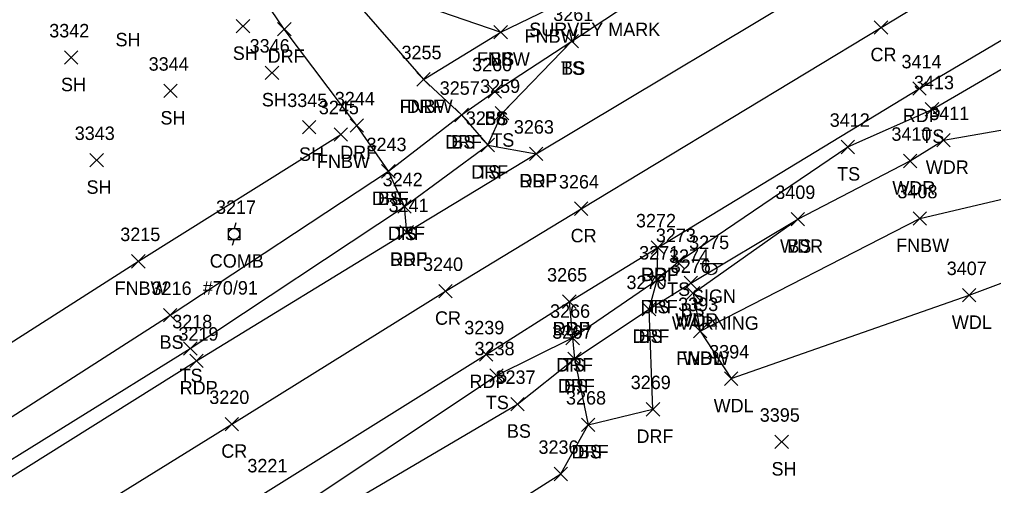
# Model space of a CAD drawing. Extents: x 1443590 to 1445966, y 578314 to 580556.
# Drawn here: x 1443948 to 1444092.8, y 578792.7 to 578862 of the extents above; entities that cross this region are included whole.
import ezdxf

# ---------------------------------------------------------------- set-up
doc = ezdxf.new("R2010")
doc.units = 0
for name, color, linetype in [('L_A', 7, 'Continuous'), ('L_I', 7, 'Continuous'), ('L_TIC', 7, 'Continuous'), ('LAWA', 7, 'Continuous'), ('LELB', 7, 'Continuous'), ('LFNC', 7, 'Continuous'), ('P_A', 7, 'Continuous'), ('P_I', 7, 'Continuous'), ('P_TIC', 7, 'Continuous'), ('PET', 7, 'Continuous'), ('PRC', 7, 'Continuous'), ('R_A', 7, 'Continuous'), ('R_I', 7, 'Continuous'), ('R_TIC', 7, 'Continuous'), ('RDF', 7, 'Continuous'), ('S_A', 7, 'Continuous'), ('S_C', 7, 'Continuous'), ('S_I', 7, 'Continuous'), ('SSGN', 7, 'Continuous'), ('U_A', 7, 'Continuous'), ('U_C', 7, 'Continuous'), ('U_I', 7, 'Continuous'), ('UP', 7, 'Continuous')]:
    doc.layers.add(name, color=color, linetype=linetype)

msp = doc.modelspace()

# ---------------------------------------------------------------- linework, layer by layer
at = {"layer": 'L_TIC'}
for points in [[(1443980.21, 578859.99), (1443982.21, 578861.99)], [(1443982.21, 578859.99), (1443980.21, 578861.99)], [(1444018.51, 578859.12), (1444020.51, 578861.12)], [(1444020.51, 578859.12), (1444018.51, 578861.12)], [(1444018.51, 578859.12), (1444020.51, 578861.12)], [(1444020.51, 578859.12), (1444018.51, 578861.12)], [(1444029.07, 578857.77), (1444031.07, 578859.77)], [(1444031.07, 578857.77), (1444029.07, 578859.77)], [(1444029.07, 578857.77), (1444031.07, 578859.77)], [(1444031.07, 578857.77), (1444029.07, 578859.77)], [(1443954.67, 578855.33), (1443956.67, 578857.33)], [(1443956.67, 578855.33), (1443954.67, 578857.33)], [(1443984.52, 578853.07), (1443986.52, 578855.07)], [(1443986.52, 578853.07), (1443984.52, 578855.07)], [(1444007.03, 578852.09), (1444009.03, 578854.09)], [(1444009.03, 578852.09), (1444007.03, 578854.09)], [(1443969.45, 578850.38), (1443971.45, 578852.38)], [(1443971.45, 578850.38), (1443969.45, 578852.38)], [(1444017.65, 578850.29), (1444019.65, 578852.29)], [(1444019.65, 578850.29), (1444017.65, 578852.29)], [(1444012.71, 578846.8), (1444014.71, 578848.8)], [(1444014.71, 578846.8), (1444012.71, 578848.8)], [(1444018.71, 578847.08), (1444020.71, 578849.08)], [(1444020.71, 578847.08), (1444018.71, 578849.08)], [(1444082.63, 578847.63), (1444084.63, 578849.63)], [(1444084.63, 578847.63), (1444082.63, 578849.63)], [(1443990.05, 578844.98), (1443992.05, 578846.98)], [(1443992.05, 578844.98), (1443990.05, 578846.98)], [(1443994.74, 578843.91), (1443996.74, 578845.91)], [(1443996.74, 578843.91), (1443994.74, 578845.91)], [(1444016.59, 578842.33), (1444018.59, 578844.33)], [(1444018.59, 578842.33), (1444016.59, 578844.33)], [(1444084.34, 578843.04), (1444086.34, 578845.04)], [(1444086.34, 578843.04), (1444084.34, 578845.04)], [(1444070.11, 578842.04), (1444072.11, 578844.04)], [(1444072.11, 578842.04), (1444070.11, 578844.04)], [(1443958.46, 578840.08), (1443960.46, 578842.08)], [(1443960.46, 578840.08), (1443958.46, 578842.08)], [(1444079.37, 578839.96), (1444081.37, 578841.96)], [(1444081.37, 578839.96), (1444079.37, 578841.96)], [(1444001.82, 578838.42), (1444003.82, 578840.42)], [(1444003.82, 578838.42), (1444001.82, 578840.42)], [(1444004.23, 578833.2), (1444006.23, 578835.2)], [(1444006.23, 578833.2), (1444004.23, 578835.2)], [(1444062.67, 578831.31), (1444064.67, 578833.31)], [(1444064.67, 578831.31), (1444062.67, 578833.31)], [(1444062.67, 578831.31), (1444064.67, 578833.31)], [(1444064.67, 578831.31), (1444062.67, 578833.31)], [(1444080.82, 578831.41), (1444082.82, 578833.41)], [(1444082.82, 578831.41), (1444080.82, 578833.41)], [(1443964.66, 578825.05), (1443966.66, 578827.05)], [(1443966.66, 578825.05), (1443964.66, 578827.05)], [(1444044.84, 578824.91), (1444046.84, 578826.91)], [(1444046.84, 578824.91), (1444044.84, 578826.91)], [(1444041.78, 578822.31), (1444043.78, 578824.31)], [(1444043.78, 578822.31), (1444041.78, 578824.31)], [(1444046.79, 578821.82), (1444048.79, 578823.82)], [(1444048.79, 578821.82), (1444046.79, 578823.82)], [(1444047.1, 578820.32), (1444049.1, 578822.32)], [(1444049.1, 578820.32), (1444047.1, 578822.32)], [(1444047.1, 578820.32), (1444049.1, 578822.32)], [(1444049.1, 578820.32), (1444047.1, 578822.32)], [(1444088.15, 578820), (1444090.15, 578822)], [(1444090.15, 578820), (1444088.15, 578822)], [(1444040.56, 578817.92), (1444042.56, 578819.92)], [(1444042.56, 578817.92), (1444040.56, 578819.92)], [(1443969.37, 578817.04), (1443971.37, 578819.04)], [(1443971.37, 578817.04), (1443969.37, 578819.04)], [(1444048.15, 578814.65), (1444050.15, 578816.65)], [(1444050.15, 578814.65), (1444048.15, 578816.65)], [(1444048.15, 578814.65), (1444050.15, 578816.65)], [(1444050.15, 578814.65), (1444048.15, 578816.65)], [(1444029.21, 578813.65), (1444031.21, 578815.65)], [(1444031.21, 578813.65), (1444029.21, 578815.65)], [(1443972.38, 578812.08), (1443974.38, 578814.08)], [(1443974.38, 578812.08), (1443972.38, 578814.08)], [(1444029.48, 578810.54), (1444031.48, 578812.54)], [(1444031.48, 578810.54), (1444029.48, 578812.54)], [(1444017.89, 578808.07), (1444019.89, 578810.07)], [(1444019.89, 578808.07), (1444017.89, 578810.07)], [(1444052.76, 578807.6), (1444054.76, 578809.6)], [(1444054.76, 578807.6), (1444052.76, 578809.6)], [(1444021, 578803.82), (1444023, 578805.82)], [(1444023, 578803.82), (1444021, 578805.82)], [(1444031.53, 578800.75), (1444033.53, 578802.75)], [(1444033.53, 578800.75), (1444031.53, 578802.75)], [(1444060.28, 578798.2), (1444062.28, 578800.2)], [(1444062.28, 578798.2), (1444060.28, 578800.2)], [(1444027.44, 578793.43), (1444029.44, 578795.43)], [(1444029.44, 578793.43), (1444027.44, 578795.43)]]:
    msp.add_lwpolyline(points, dxfattribs=at)
at = {"layer": 'LAWA'}
for points in [[(1444048.1, 578821.32), (1444063.67, 578832.31), (1444080.37, 578840.96), (1444085.34, 578844.04), (1444109.18, 578848.22), (1444135.34, 578861.47), (1444163.11, 578880.72), (1444179.57, 578893.49), (1444193.41, 578903.29), (1444214.9, 578918.81), (1444217.38, 578923.7), (1444222.65, 578929.51), (1444230.19, 578931.19), (1444234.32, 578936.96), (1444238.17, 578925.12), (1444234.94, 578915.96)], [(1444048.1, 578821.32), (1444049.15, 578815.65), (1444053.76, 578808.6), (1444089.15, 578821), (1444115.87, 578831.04), (1444149.45, 578834.28), (1444175.65, 578843.43), (1444202.18, 578846.34), (1444218.5, 578835.02), (1444228, 578822.21), (1444234.72, 578800.9), (1444237.58, 578781.4), (1444240.48, 578772.04)]]:
    msp.add_lwpolyline(points, dxfattribs=at)
at = {"layer": 'LELB'}
for points in [[(1443938.52, 578791.48), (1443973.38, 578813.08), (1444005.23, 578834.2), (1444017.59, 578843.33), (1444019.71, 578848.08), (1444030.07, 578858.77), (1444048.25, 578870.77), (1444059.47, 578877.54), (1444084.03, 578888.38), (1444116.13, 578900.62), (1444133.65, 578911.54), (1444146.41, 578917.11), (1444149.51, 578920.45), (1444149.93, 578925.58), (1444153.52, 578930.88), (1444162.25, 578930.68), (1444174.13, 578936.01), (1444189.83, 578945.52), (1444198.3, 578950.86), (1444200.25, 578947.99), (1444203.06, 578948.48)], [(1443615.53, 578549.09), (1443647.15, 578571.87), (1443656.71, 578577.24), (1443699.78, 578605.86), (1443739.16, 578631.36), (1443774.01, 578653.63), (1443806.33, 578675.43), (1443846.66, 578699.7), (1443880.84, 578720.78), (1443915.45, 578744.08), (1443953.64, 578767.01), (1443986.4, 578787.39), (1444018.89, 578809.07), (1444030.21, 578814.65), (1444042.78, 578823.31), (1444045.84, 578825.91), (1444071.11, 578843.04), (1444083.63, 578848.63), (1444101.33, 578858.93), (1444132.81, 578873.64), (1444159.48, 578890.92), (1444189.04, 578910.16), (1444210.73, 578922.71), (1444214.87, 578926.32)], [(1443994.39, 578868.79), (1444019.51, 578860.12)], [(1443598.08, 578578.97), (1443630.15, 578597.86), (1443636.56, 578601.95), (1443682.3, 578633.7), (1443721.18, 578657.98), (1443758.09, 578682.95), (1443790.68, 578702.48), (1443830, 578727.26), (1443864.08, 578751.06), (1443899.99, 578773.27), (1443935.63, 578795.8), (1443970.37, 578818.04), (1444002.82, 578839.42), (1444013.71, 578847.8), (1444018.65, 578851.29), (1444030.07, 578858.77)], [(1443617.38, 578545.93), (1443649.59, 578568.34), (1443659.37, 578572.13), (1443703.15, 578599.79), (1443742.08, 578627.42), (1443775.99, 578650.05), (1443809.17, 578670.17), (1443847.87, 578696.41), (1443882.88, 578718.02), (1443917, 578740.41), (1443955.43, 578764.28), (1443988.08, 578784.83), (1444022, 578804.82), (1444030.48, 578811.54), (1444041.56, 578818.92), (1444047.79, 578822.82), (1444063.67, 578832.31)], [(1443707.24, 578593.68), (1443747.78, 578617.37), (1443781.43, 578641.01), (1443814.18, 578660.08), (1443852.96, 578688.17), (1443888.41, 578709.13), (1443921.62, 578733.3), (1443961.2, 578754.18), (1443994.65, 578773), (1444028.44, 578794.43), (1444032.53, 578801.75)]]:
    msp.add_lwpolyline(points, dxfattribs=at)
at = {"layer": 'LFNC'}
for points in [[(1444008.03, 578853.09), (1444019.51, 578860.12), (1444026.6, 578863.53), (1444041.29, 578874.04), (1444045.2, 578875.82), (1444057.59, 578882.55), (1444080.64, 578894.32), (1444110.52, 578908.89), (1444116.81, 578913.3)], [(1444049.15, 578815.65), (1444081.82, 578832.41), (1444112.31, 578839.58), (1444143.92, 578843.39), (1444172.92, 578854.56)], [(1443632.19, 578609.42), (1443678.23, 578640.34), (1443716.84, 578665.76), (1443753.55, 578689.96), (1443784.42, 578710.35), (1443825.24, 578737.4), (1443860.1, 578759.1), (1443895.87, 578781.95), (1443931.05, 578803.95), (1443965.66, 578826.05), (1443995.74, 578844.91)]]:
    msp.add_lwpolyline(points, dxfattribs=at)
at = {"layer": 'P_TIC'}
for points in [[(1444075.05, 578859.79), (1444077.05, 578861.79)], [(1444077.05, 578859.79), (1444075.05, 578861.79)], [(1444080.78, 578850.73), (1444082.78, 578852.73)], [(1444082.78, 578850.73), (1444080.78, 578852.73)], [(1444023.78, 578841.02), (1444025.78, 578843.02)], [(1444025.78, 578841.02), (1444023.78, 578843.02)], [(1444030.47, 578832.87), (1444032.47, 578834.87)], [(1444032.47, 578832.87), (1444030.47, 578834.87)], [(1444004.54, 578829.37), (1444006.54, 578831.37)], [(1444006.54, 578829.37), (1444004.54, 578831.37)], [(1444041.88, 578827.09), (1444043.88, 578829.09)], [(1444043.88, 578827.09), (1444041.88, 578829.09)], [(1444010.31, 578820.61), (1444012.31, 578822.61)], [(1444012.31, 578820.61), (1444010.31, 578822.61)], [(1444028.71, 578819.04), (1444030.71, 578821.04)], [(1444030.71, 578819.04), (1444028.71, 578821.04)], [(1443973.31, 578810.25), (1443975.31, 578812.25)], [(1443975.31, 578810.25), (1443973.31, 578812.25)], [(1444016.37, 578811.19), (1444018.37, 578813.19)], [(1444018.37, 578811.19), (1444016.37, 578813.19)], [(1443978.55, 578800.84), (1443980.55, 578802.84)], [(1443980.55, 578800.84), (1443978.55, 578802.84)]]:
    msp.add_lwpolyline(points, dxfattribs=at)
at = {"layer": 'PET'}
for points in [[(1443601.36, 578573.38), (1443632.23, 578593.39), (1443639.99, 578598.09), (1443685.58, 578628.02), (1443724.74, 578653.09), (1443761.98, 578676.74), (1443793.7, 578697.2), (1443832.46, 578722.27), (1443867.74, 578744.22), (1443903.66, 578767.03), (1443939.74, 578789.58), (1443974.31, 578811.25), (1444005.54, 578830.37), (1444024.78, 578842.02), (1444070.83, 578869.64), (1444088.82, 578880.14), (1444118.02, 578897.28), (1444147.48, 578914.76), (1444176.13, 578931.32), (1444203.82, 578947.29), (1444208.88, 578939.04), (1444214.07, 578930.35)], [(1443612.4, 578554.37), (1443645.04, 578575.45), (1443657.24, 578583.2), (1443697.44, 578609.18), (1443737.28, 578634.55), (1443772.29, 578657.29), (1443804.75, 578678.07), (1443844.06, 578703.73), (1443878.04, 578725.08), (1443913.76, 578747.61), (1443950.95, 578770.86), (1443984.55, 578791.67), (1444017.37, 578812.19), (1444029.71, 578820.04), (1444042.88, 578828.09), (1444081.78, 578851.73), (1444099.65, 578862.29), (1444128.94, 578879.48), (1444156.82, 578896.17), (1444186.94, 578914.09), (1444214.07, 578930.35)]]:
    msp.add_lwpolyline(points, dxfattribs=at)
at = {"layer": 'PRC'}
msp.add_lwpolyline([(1443607.19, 578563.71), (1443645.74, 578588.68), (1443691.8, 578618.64), (1443730.92, 578643.94), (1443766.58, 578667.23), (1443799.08, 578688.06), (1443838.06, 578712.83), (1443872.72, 578734.91), (1443908.54, 578757.41), (1443944.72, 578780.26), (1443979.55, 578801.84), (1444011.31, 578821.61), (1444031.47, 578833.87), (1444076.05, 578860.79), (1444093.92, 578871.67), (1444123.23, 578888.92), (1444152.19, 578905.95), (1444180.96, 578922.73), (1444208.88, 578939.04)], dxfattribs=at)
at = {"layer": 'R_TIC'}
for points in [[(1443986.35, 578859.55), (1443988.35, 578861.55)], [(1443988.35, 578859.55), (1443986.35, 578861.55)], [(1444007.03, 578852.09), (1444009.03, 578854.09)], [(1444009.03, 578852.09), (1444007.03, 578854.09)], [(1444012.71, 578846.8), (1444014.71, 578848.8)], [(1444014.71, 578846.8), (1444012.71, 578848.8)], [(1443997.12, 578845.23), (1443999.12, 578847.23)], [(1443999.12, 578845.23), (1443997.12, 578847.23)], [(1444016.59, 578842.33), (1444018.59, 578844.33)], [(1444018.59, 578842.33), (1444016.59, 578844.33)], [(1444023.78, 578841.02), (1444025.78, 578843.02)], [(1444025.78, 578841.02), (1444023.78, 578843.02)], [(1444001.82, 578838.42), (1444003.82, 578840.42)], [(1444003.82, 578838.42), (1444001.82, 578840.42)], [(1444004.23, 578833.2), (1444006.23, 578835.2)], [(1444006.23, 578833.2), (1444004.23, 578835.2)], [(1444004.54, 578829.37), (1444006.54, 578831.37)], [(1444006.54, 578829.37), (1444004.54, 578831.37)], [(1444041.88, 578827.09), (1444043.88, 578829.09)], [(1444043.88, 578827.09), (1444041.88, 578829.09)], [(1444041.78, 578822.31), (1444043.78, 578824.31)], [(1444043.78, 578822.31), (1444041.78, 578824.31)], [(1444028.71, 578819.04), (1444030.71, 578821.04)], [(1444030.71, 578819.04), (1444028.71, 578821.04)], [(1444040.56, 578817.92), (1444042.56, 578819.92)], [(1444042.56, 578817.92), (1444040.56, 578819.92)], [(1444029.21, 578813.65), (1444031.21, 578815.65)], [(1444031.21, 578813.65), (1444029.21, 578815.65)], [(1444029.48, 578810.54), (1444031.48, 578812.54)], [(1444031.48, 578810.54), (1444029.48, 578812.54)], [(1444041.15, 578803.05), (1444043.15, 578805.05)], [(1444043.15, 578803.05), (1444041.15, 578805.05)], [(1444031.53, 578800.75), (1444033.53, 578802.75)], [(1444033.53, 578800.75), (1444031.53, 578802.75)]]:
    msp.add_lwpolyline(points, dxfattribs=at)
at = {"layer": 'RDF'}
for points in [[(1443966.18, 578906.12), (1443972.09, 578897.91), (1443978.46, 578889.4), (1443989.8, 578874.36), (1443994.39, 578868.79), (1444008.03, 578853.09), (1444013.71, 578847.8), (1444017.59, 578843.33), (1444024.78, 578842.02)], [(1444005.54, 578830.37), (1444005.23, 578834.2), (1444002.82, 578839.42), (1443998.12, 578846.23), (1443987.35, 578860.55), (1443977.51, 578875.06), (1443965.28, 578891.59), (1443957.31, 578900.74)], [(1444029.71, 578820.04), (1444030.21, 578814.65), (1444030.48, 578811.54), (1444032.53, 578801.75), (1444042.15, 578804.05), (1444041.56, 578818.92), (1444042.78, 578823.31), (1444042.88, 578828.09)]]:
    msp.add_lwpolyline(points, dxfattribs=at)
at = {"layer": 'SSGN'}
for p, q in [((1444049.16, 578825.71), (1444052.49, 578825.71)), ((1444050.8, 578824.88), (1444050.8, 578824.88))]:
    msp.add_line(p, q, dxfattribs=at)
msp.add_circle((1444050.8, 578824.88), 0.833, dxfattribs=at)
at = {"layer": 'UP'}
for p, q in [((1443980.14, 578831.76), (1443979.89, 578830.93)), ((1443979.05, 578829.26), (1443979.05, 578830.93)), ((1443979.05, 578830.93), (1443980.72, 578830.93)), ((1443979.89, 578830.1), (1443979.89, 578830.1)), ((1443980.72, 578830.93), (1443980.72, 578829.26)), ((1443980.72, 578829.26), (1443979.05, 578829.26)), ((1443979.64, 578828.43), (1443979.89, 578829.26))]:
    msp.add_line(p, q, dxfattribs=at)
msp.add_circle((1443979.89, 578830.1), 0.833, dxfattribs=at)

# ---------------------------------------------------------------- texts
at = {"layer": 'L_A'}
for s, p in [('SH', (1443962.26, 578858)), ('FNBW', (1444023.07, 578858.53)), ('SH', (1443979.69, 578855.99)), ('FNBW', (1444015.98, 578855.12)), ('BS', (1444017.95, 578855.12)), ('TS', (1444028.48, 578853.77)), ('BS', (1444028.51, 578853.77)), ('SH', (1443954.16, 578851.33)), ('SH', (1443984.01, 578849.07)), ('FNBW', (1444004.5, 578848.09)), ('SH', (1443968.94, 578846.38)), ('BS', (1444017.09, 578846.29)), ('TS', (1444082.04, 578843.63)), ('BS', (1444012.16, 578842.8)), ('TS', (1444018.12, 578843.08)), ('SH', (1443989.54, 578840.98)), ('FNBW', (1443992.21, 578839.91)), ('TS', (1444016, 578838.33)), ('TS', (1444069.52, 578838.04)), ('WDR', (1444082.7, 578839.04)), ('SH', (1443957.95, 578836.08)), ('WDR', (1444077.73, 578835.96)), ('BS', (1444001.27, 578834.42)), ('TS', (1444003.63, 578829.2)), ('WDR', (1444061.04, 578827.31)), ('BS', (1444062.12, 578827.31)), ('FNBW', (1444078.29, 578827.41)), ('FNBW', (1443962.13, 578821.05)), ('TS', (1444044.25, 578820.91)), ('TS', (1444041.19, 578818.31)), ('BS', (1444046.23, 578817.82)), ('WDR', (1444045.47, 578816.32)), ('WDL', (1444045.52, 578816.32)), ('WDL', (1444086.57, 578816)), ('BS', (1444040, 578813.92)), ('BS', (1443968.81, 578813.04)), ('FNBW', (1444045.62, 578810.65)), ('WDL', (1444046.57, 578810.65)), ('TS', (1444028.62, 578809.65)), ('TS', (1443971.79, 578808.08)), ('BS', (1444028.92, 578806.54)), ('TS', (1444017.3, 578804.07)), ('WDL', (1444051.17, 578803.6)), ('BS', (1444020.44, 578799.82)), ('BS', (1444030.97, 578796.75)), ('SH', (1444059.77, 578794.2))]:
    msp.add_text(s, height=2, dxfattribs=at).set_placement(p)
at = {"layer": 'L_I'}
for s, p in [('3261', (1444027.33, 578861.77)), ('3261', (1444027.33, 578861.77)), ('3342', (1443952.41, 578859.33)), ('3346', (1443982.2, 578857.07)), ('3255', (1444004.77, 578856.09)), ('3344', (1443967.19, 578854.38)), ('3260', (1444015.26, 578854.29)), ('3257', (1444010.45, 578850.8)), ('3259', (1444016.45, 578851.08)), ('3413', (1444080.94, 578851.63)), ('3345', (1443987.79, 578848.98)), ('3245', (1443992.48, 578847.91)), ('3411', (1444083.21, 578847.04)), ('3258', (1444014.33, 578846.33)), ('3412', (1444068.42, 578846.04)), ('3343', (1443956.2, 578844.08)), ('3410', (1444077.59, 578843.96)), ('3243', (1443999.57, 578842.42)), ('3242', (1444001.97, 578837.2)), ('3409', (1444060.33, 578835.31)), ('3409', (1444060.33, 578835.31)), ('3408', (1444078.48, 578835.41)), ('3215', (1443962.97, 578829.05)), ('3273', (1444042.58, 578828.91)), ('3271', (1444040.09, 578826.31)), ('3274', (1444044.53, 578825.82)), ('3276', (1444044.79, 578824.32)), ('3276', (1444044.79, 578824.32)), ('3407', (1444085.81, 578824)), ('3270', (1444038.21, 578821.92)), ('3216', (1443967.62, 578821.04)), ('3266', (1444026.85, 578817.65)), ('3393', (1444045.89, 578818.65)), ('3393', (1444045.89, 578818.65)), ('3218', (1443970.69, 578816.08)), ('3267', (1444027.17, 578814.54)), ('3238', (1444015.63, 578812.07)), ('3394', (1444050.5, 578811.6)), ('3237', (1444018.74, 578807.82)), ('3268', (1444029.22, 578804.75)), ('3395', (1444058.02, 578802.2)), ('3236', (1444025.13, 578797.43))]:
    msp.add_text(s, height=2, dxfattribs=at).set_placement(p)
at = {"layer": 'P_A'}
for s, p in [('CR', (1444074.48, 578855.79)), ('RDP', (1444079.27, 578846.73)), ('RDP', (1444022.27, 578837.02)), ('CR', (1444029.91, 578828.87)), ('RDP', (1444003.03, 578825.37)), ('RDP', (1444040.37, 578823.09)), ('CR', (1444009.75, 578816.61)), ('RDP', (1444027.2, 578815.04)), ('RDP', (1443971.8, 578806.25)), ('RDP', (1444014.86, 578807.19)), ('CR', (1443977.98, 578796.84))]:
    msp.add_text(s, height=2, dxfattribs=at).set_placement(p)
at = {"layer": 'P_I'}
for s, p in [('3414', (1444079.09, 578854.73)), ('3263', (1444021.47, 578845.02)), ('3264', (1444028.17, 578836.87)), ('3241', (1444002.85, 578833.37)), ('3272', (1444039.62, 578831.09)), ('3240', (1444007.97, 578824.61)), ('3265', (1444026.41, 578823.04)), ('3239', (1444014.1, 578815.19)), ('3219', (1443971.61, 578814.25)), ('3220', (1443976.2, 578804.84)), ('3221', (1443981.86, 578794.67))]:
    msp.add_text(s, height=2, dxfattribs=at).set_placement(p)
at = {"layer": 'R_A'}
for p in [(1443984.88, 578855.55), (1444005.56, 578848.09), (1444011.25, 578842.8), (1443995.66, 578841.23), (1444015.13, 578838.33), (1444022.31, 578837.02), (1444000.36, 578834.42), (1444002.76, 578829.2), (1444003.07, 578825.37), (1444040.42, 578823.09), (1444040.32, 578818.31), (1444027.25, 578815.04), (1444039.09, 578813.92), (1444027.75, 578809.65), (1444028.01, 578806.54), (1444039.69, 578799.05), (1444030.06, 578796.75)]:
    msp.add_text('DRF', height=2, dxfattribs=at).set_placement(p)
at = {"layer": 'R_I'}
for s, p in [('3255', (1444004.77, 578856.09)), ('3257', (1444010.45, 578850.8)), ('3244', (1443994.86, 578849.23)), ('3258', (1444014.33, 578846.33)), ('3263', (1444021.47, 578845.02)), ('3243', (1443999.57, 578842.42)), ('3242', (1444001.97, 578837.2)), ('3241', (1444002.85, 578833.37)), ('3272', (1444039.62, 578831.09)), ('3271', (1444040.09, 578826.31)), ('3265', (1444026.41, 578823.04)), ('3270', (1444038.21, 578821.92)), ('3266', (1444026.85, 578817.65)), ('3267', (1444027.17, 578814.54)), ('3269', (1444038.84, 578807.05)), ('3268', (1444029.22, 578804.75))]:
    msp.add_text(s, height=2, dxfattribs=at).set_placement(p)
at = {"layer": 'S_A'}
msp.add_text('SIGN', height=2, dxfattribs=at).set_placement((1444047.94, 578819.86))
at = {"layer": 'S_C'}
for s, p in [('SURVEY MARK', (1444023.76, 578859.52)), ('WARNING', (1444044.95, 578815.86))]:
    msp.add_text(s, height=2, dxfattribs=at).set_placement(p)
at = {"layer": 'S_I'}
msp.add_text('3275', height=2, dxfattribs=at).set_placement((1444047.52, 578827.86))
at = {"layer": 'U_A'}
msp.add_text('COMB', height=2, dxfattribs=at).set_placement((1443976.27, 578825.1))
at = {"layer": 'U_C'}
msp.add_text('#70/91', height=2, dxfattribs=at).set_placement((1443975.24, 578821.1))
at = {"layer": 'U_I'}
msp.add_text('3217', height=2, dxfattribs=at).set_placement((1443977.2, 578833.1))

doc.saveas('drawing.dxf')
